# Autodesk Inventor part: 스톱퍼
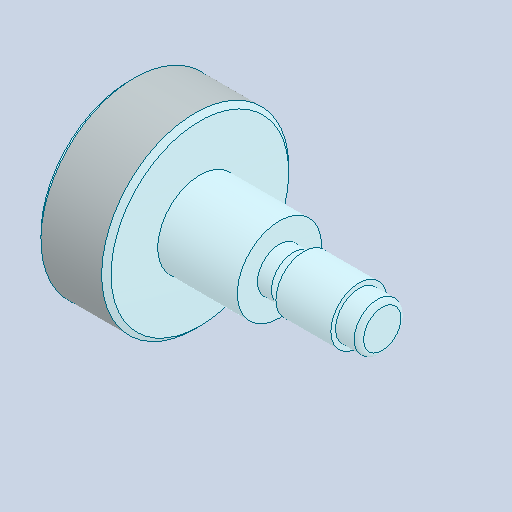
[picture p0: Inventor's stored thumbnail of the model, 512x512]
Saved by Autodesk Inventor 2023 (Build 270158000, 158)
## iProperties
Created: 2024-07
Part Number: 스톱퍼
Material: 강철, 탄소
Document SubType Name: Modeling
Designer: home
Density: 7.85 g/cm^3
Appearance: 기본값
Author: jhkim
Sending System: Autodesk Inventor 2025
Preprocessor: ST-DEVELOPER v20
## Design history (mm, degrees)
feature "솔리드1"
node "솔리드2"
